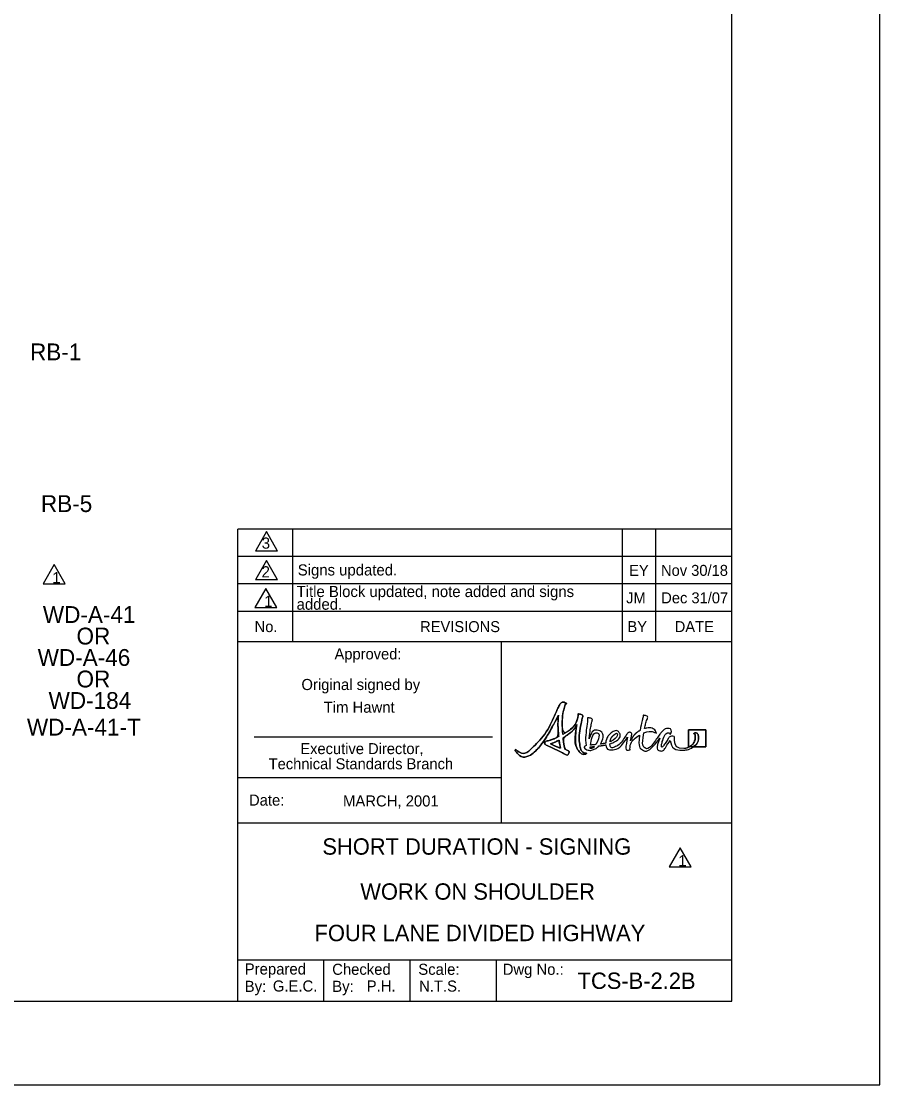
# Model space of a CAD drawing. Extents: x 1333 to 1549, y 120 to 399.
# Drawn here: x 1438.4 to 1549.4, y 119.8 to 257.2 of the extents above; entities that cross this region are included whole.
import ezdxf

# ---------------------------------------------------------------- set-up
doc = ezdxf.new("R2010")
doc.units = 0
for name, color, linetype in [('Level 1', 7, 'Continuous'), ('Level 10', 7, 'Continuous'), ('Level 2', 7, 'Continuous'), ('Level 22', 7, 'Continuous'), ('Level 44', 7, 'Continuous'), ('Level 45', 7, 'Continuous'), ('Level 53', 7, 'Continuous'), ('Level 60', 7, 'Continuous'), ('Level 63', 7, 'Continuous'), ('Level 7', 7, 'Continuous')]:
    doc.layers.add(name, color=color, linetype=linetype)

msp = doc.modelspace()

# ---------------------------------------------------------------- linework, layer by layer
at = {"layer": 'Level 1'}
for p, q in [((1466.39, 130.56), (1466.39, 177.03)), ((1500.44, 177.03), (1500.44, 153.62)), ((1466.39, 159.47), (1500.44, 159.47)), ((1466.39, 153.62), (1530.24, 153.62)), ((1466.39, 135.88), (1530.24, 135.88)), ((1477.52, 130.56), (1477.52, 135.88)), ((1488.65, 130.56), (1488.65, 135.88)), ((1499.78, 135.88), (1499.78, 130.56))]:
    msp.add_line(p, q, dxfattribs=at)
for points in [[(1442.64, 186.98), (1441.22, 184.51), (1444.06, 184.51)], [(1523.56, 150.39), (1522.14, 147.92), (1524.98, 147.92)]]:
    msp.add_lwpolyline(points, close=True, dxfattribs=at)
at = {"layer": 'Level 10'}
msp.add_line((1530.24, 130.56), (1530.24, 130.56), dxfattribs=at)
msp.add_line((1530.24, 130.56), (1530.24, 130.56), dxfattribs=at)
at = {"layer": 'Level 2'}
msp.add_line((1500.44, 177.03), (1500.44, 177.03), dxfattribs=at)
at = {"layer": 'Level 22'}
msp.add_line((1481.86, 130.56), (1481.86, 130.56), dxfattribs=at)
at = {"layer": 'Level 44'}
for p, q in [((1530.27, 191.58), (1466.38, 191.58)), ((1530.27, 188.03), (1466.38, 188.03)), ((1530.27, 184.48), (1466.38, 184.48)), ((1530.27, 180.93), (1466.38, 180.93)), ((1466.39, 177.03), (1530.27, 177.03))]:
    msp.add_line(p, q, dxfattribs=at)
msp.add_lwpolyline([(1470.01, 183.91), (1468.59, 181.44), (1471.43, 181.44)], close=True, dxfattribs=at)
at = {"layer": 'Level 45'}
msp.add_line((1500.46, 177.03), (1500.46, 177.03), dxfattribs=at)
at = {"layer": 'Level 53'}
msp.add_line((1525.26, 163.41), (1524.71, 163.41), dxfattribs=at)
msp.add_lwpolyline([(1525.26, 163.41), (1526.88, 163.41), (1526.88, 165.64), (1524.65, 165.64), (1524.65, 163.41), (1524.71, 163.41)], dxfattribs=at)
for points, degree in [([(1511.28, 162.6), (1511.04, 162.64), (1510.72, 162.97), (1510.63, 163.5), (1510.46, 164.47), (1510.56, 165.42), (1510.84, 166.84), (1510.89, 167.11), (1511.08, 167.58), (1510.49, 167.67), (1510.31, 167.7), (1510.41, 167.61), (1510.35, 167.36), (1510.13, 166.3), (1509.26, 165.54), (1508.39, 165.03), (1508.3, 166.24), (1508.34, 167.59), (1508.57, 168.41), (1508.76, 169.11), (1508.99, 168.98), (1508.71, 169.13), (1508.41, 169.28), (1508.09, 169.08), (1507.83, 168.56), (1507.57, 168.04), (1506.37, 165.22), (1504.46, 163.32), (1503.48, 162.35), (1502.6, 162.85), (1502.42, 163), (1502.27, 163.12), (1502.22, 162.93), (1502.4, 162.74), (1503.19, 161.89), (1504.35, 162.38), (1504.77, 162.8), (1505.93, 163.96), (1507.28, 166.46), (1507.83, 167.52), (1507.78, 166.93), (1507.76, 165.92), (1507.87, 164.75), (1507.28, 164.46), (1506.75, 164.29), (1506.5, 164.23), (1506.23, 164.15), (1506.06, 164.04), (1506.06, 163.92), (1506.05, 163.78), (1506.23, 163.66), (1506.5, 163.54), (1506.97, 163.32), (1508.34, 162.67), (1508.68, 162.47), (1508.96, 162.3), (1509.11, 162.44), (1509.19, 162.62), (1509.3, 162.85), (1509, 162.99), (1508.7, 163.08), (1508.58, 163.48), (1508.49, 164.01), (1508.43, 164.6), (1509.13, 165.03), (1509.82, 165.6), (1510.21, 166.32), (1510.11, 165.72), (1509.86, 163.69), (1510.5, 162.83), (1510.64, 162.64), (1510.95, 162.44), (1511.26, 162.47), (1511.4, 162.48), (1511.47, 162.57), (1511.46, 162.6), (1511.44, 162.63), (1511.36, 162.59), (1511.28, 162.6)], 3), ([(1508.39, 165.03), (1508.3, 166.24), (1508.34, 167.59), (1508.57, 168.41), (1508.76, 169.11), (1508.99, 168.98), (1508.71, 169.13), (1508.41, 169.28), (1508.09, 169.08), (1507.83, 168.56), (1507.57, 168.04), (1506.37, 165.22), (1504.46, 163.32), (1503.48, 162.35), (1502.6, 162.85), (1502.42, 163), (1502.27, 163.12), (1502.22, 162.93), (1502.4, 162.74), (1503.19, 161.89), (1504.35, 162.38), (1504.77, 162.8), (1505.93, 163.96), (1507.28, 166.46), (1507.83, 167.52)], 3), ([(1507.83, 167.52), (1507.78, 166.93), (1507.76, 165.92), (1507.87, 164.75)], 2), ([(1511.28, 162.6), (1511.04, 162.64), (1510.72, 162.97), (1510.63, 163.5), (1510.46, 164.47), (1510.56, 165.42), (1510.84, 166.84), (1510.89, 167.11), (1511.08, 167.58), (1510.49, 167.67), (1510.31, 167.7), (1510.41, 167.61), (1510.35, 167.36), (1510.13, 166.3), (1509.26, 165.54), (1508.39, 165.03)], 3), ([(1511.81, 164.45), (1511.86, 165.02), (1511.95, 165.71), (1512.08, 166.35), (1512.13, 166.62), (1512.32, 167.09), (1511.73, 167.17), (1511.55, 167.2), (1511.58, 167.12), (1511.59, 166.87), (1511.61, 166.53), (1511.24, 164.49), (1511.43, 163.59)], 3), ([(1518.97, 165.79), (1519.03, 166.08), (1519.11, 166.39), (1519.19, 166.68), (1519.26, 166.95), (1519.49, 167.42), (1518.91, 167.5), (1518.73, 167.53), (1518.8, 167.44), (1518.74, 167.2), (1518.63, 166.74), (1518.49, 166.15), (1518.39, 165.55)], 3), ([(1508.43, 164.6), (1509.13, 165.03), (1509.82, 165.6), (1510.21, 166.32)], 2), ([(1510.21, 166.32), (1510.11, 165.72), (1509.86, 163.69), (1510.5, 162.83), (1510.64, 162.64), (1510.95, 162.44), (1511.26, 162.47), (1511.4, 162.48), (1511.47, 162.57), (1511.46, 162.6), (1511.44, 162.63), (1511.36, 162.59), (1511.28, 162.6)], 3), ([(1513.25, 163.78), (1513.67, 164.46), (1513.63, 165.37), (1513.02, 165.52), (1512.32, 165.7), (1511.96, 165.01), (1511.81, 164.45)], 3), ([(1511.96, 163.66), (1512.06, 164.37), (1512.43, 165.37), (1512.89, 165.21), (1513.16, 165.11), (1513.02, 164.28), (1512.68, 163.72)], 3), ([(1514.48, 163.81), (1514.57, 163.84), (1514.66, 163.87), (1514.73, 163.9), (1515.61, 164.29), (1515.92, 164.88), (1515.69, 165.24), (1515.48, 165.58), (1514.87, 165.48), (1514.39, 164.97), (1514.15, 164.72), (1513.97, 164.29), (1513.95, 163.9)], 3), ([(1517.15, 164.22), (1517.21, 164.5), (1517.29, 164.8), (1517.3, 165.01), (1517.31, 165.23), (1517.16, 165.28), (1517.1, 165.29), (1516.97, 165.33), (1516.82, 165.27), (1516.67, 165.05), (1516.32, 164.56), (1515.87, 163.77), (1515.19, 163.44), (1514.7, 163.2), (1514.49, 163.44), (1514.48, 163.81)], 3), ([(1514.95, 164.93), (1515.24, 165.2), (1515.39, 165.18), (1515.43, 165.11), (1515.51, 164.95), (1515.17, 164.39), (1514.5, 164.08)], 3), ([(1518.39, 165.55), (1517.92, 165.28), (1517.47, 164.82), (1517.15, 164.22)], 2), ([(1524.02, 163.22), (1523.11, 163.22), (1522.87, 163.93), (1522.83, 164.28), (1522.8, 164.51), (1522.85, 164.85), (1522.44, 164.81), (1522.16, 164.78), (1521.9, 164.22), (1521.54, 163.76), (1521.24, 163.36), (1521.1, 163.4), (1521.17, 163.74), (1521.26, 164.17), (1521.62, 165.18), (1522.03, 165.25), (1522.22, 165.28), (1522.28, 164.95), (1522.37, 165.16), (1522.46, 165.37), (1522.38, 165.82), (1521.95, 165.82), (1521.66, 165.82), (1521.3, 165.5), (1521.01, 165.14), (1520.76, 164.83), (1519.47, 162.94), (1518.93, 163.35), (1518.68, 163.54), (1518.7, 164.32), (1518.86, 165.23)], 3), ([(1518.86, 165.23), (1519.5, 165.48), (1520.03, 165.4), (1520.33, 165.26), (1520.48, 165.18), (1520.5, 165.19), (1520.44, 165.36), (1520.34, 165.6), (1519.83, 165.97), (1519.02, 165.8), (1519.01, 165.8), (1518.99, 165.79), (1518.97, 165.79)], 3), ([(1524.65, 165.64), (1524.65, 165.64), (1524.65, 163.41), (1524.65, 163.41), (1524.65, 163.41), (1524.71, 163.41), (1524.71, 163.41), (1525.2, 163.7), (1525.52, 164.26), (1525.52, 164.71), (1525.52, 165.11), (1525.31, 165.09), (1525.33, 165.14), (1525.4, 165.3), (1525.9, 165.21), (1525.92, 164.65), (1525.95, 164.18), (1525.7, 163.73), (1525.26, 163.41), (1525.26, 163.41), (1526.88, 163.41), (1526.88, 163.41), (1526.88, 163.41), (1526.88, 165.64), (1526.88, 165.64), (1526.88, 165.64), (1524.65, 165.64), (1524.65, 165.64)], 3), ([(1524.71, 163.41), (1525.2, 163.7), (1525.52, 164.26), (1525.52, 164.71), (1525.52, 165.11), (1525.31, 165.09), (1525.33, 165.14), (1525.4, 165.3), (1525.9, 165.21), (1525.92, 164.65), (1525.95, 164.18), (1525.7, 163.73), (1525.26, 163.41)], 3), ([(1507.87, 164.75), (1507.28, 164.46), (1506.75, 164.29), (1506.5, 164.23), (1506.23, 164.15), (1506.06, 164.04), (1506.06, 163.92), (1506.05, 163.78), (1506.23, 163.66), (1506.5, 163.54), (1506.97, 163.32), (1508.34, 162.67), (1508.68, 162.47), (1508.96, 162.3), (1509.11, 162.44), (1509.19, 162.62), (1509.3, 162.85), (1509, 162.99), (1508.7, 163.08)], 3), ([(1506.8, 163.82), (1507.11, 163.93), (1507.51, 164.09), (1507.92, 164.31)], 2), ([(1506.8, 163.82), (1507.11, 163.93), (1507.51, 164.09), (1507.92, 164.31), (1507.98, 163.84), (1508.04, 163.5), (1508.1, 163.24), (1507.8, 163.35), (1507.37, 163.53), (1506.8, 163.82)], 3), ([(1508.1, 163.24), (1507.8, 163.35), (1507.37, 163.53), (1506.8, 163.82)], 2), ([(1507.92, 164.31), (1507.98, 163.84), (1508.04, 163.5), (1508.1, 163.24)], 2), ([(1508.7, 163.08), (1508.58, 163.48), (1508.49, 164.01), (1508.43, 164.6)], 2), ([(1511.43, 163.59), (1511.18, 163.51), (1511.08, 163.32), (1511.4, 163.12), (1511.63, 162.99), (1512.12, 162.94), (1512.61, 163.19), (1512.79, 163.27), (1512.94, 163.4), (1513.07, 163.54)], 3), ([(1512.68, 163.72), (1512.45, 163.7), (1512.21, 163.67), (1511.96, 163.66)], 2), ([(1513.07, 163.54), (1513.36, 163.58), (1513.67, 163.63), (1513.96, 163.68)], 2), ([(1513.95, 163.9), (1513.75, 163.86), (1513.51, 163.82), (1513.25, 163.78)], 2), ([(1513.96, 163.68), (1514.01, 163.29), (1514.26, 162.99), (1514.86, 163.04), (1515.7, 163.12), (1516.45, 164.16), (1516.74, 164.66)], 3), ([(1514.5, 164.08), (1514.56, 164.38), (1514.72, 164.71), (1514.95, 164.93)], 2), ([(1516.74, 164.66), (1516.69, 164.13), (1516.34, 162.95), (1516.93, 163.01), (1517.17, 163.04), (1517.07, 163.07), (1517.08, 163.28), (1517.13, 163.98), (1517.72, 164.58), (1518.3, 164.95)], 3), ([(1518.3, 164.95), (1518.2, 164.08), (1518.24, 163.31), (1518.63, 163.07), (1519.35, 162.61), (1520.37, 163.8), (1520.94, 164.53)], 3), ([(1520.94, 164.53), (1520.65, 163.88), (1520.49, 163.06), (1520.92, 162.93), (1521.42, 162.78), (1521.82, 163.62), (1522.29, 164.26)], 3), ([(1522.29, 164.26), (1522.34, 163.8), (1522.65, 163.01), (1523.88, 163.01), (1524.44, 163.01), (1524.91, 163.17), (1525.26, 163.41)], 3), ([(1511.89, 163.22), (1511.92, 163.25), (1511.94, 163.29), (1511.94, 163.34), (1511.94, 163.37), (1511.94, 163.4), (1511.94, 163.43)], 3), ([(1512.09, 163.23), (1512.01, 163.21), (1511.94, 163.21), (1511.89, 163.22)], 2), ([(1511.94, 163.43), (1512.07, 163.44), (1512.26, 163.45), (1512.5, 163.48)], 2), ([(1512.5, 163.48), (1512.38, 163.34), (1512.24, 163.25), (1512.09, 163.23)], 2), ([(1524.71, 163.41), (1524.51, 163.29), (1524.27, 163.22), (1524.02, 163.22)], 2)]:
    msp.add_open_spline(points, degree=degree, dxfattribs=at)
at = {"layer": 'Level 60'}
for points in [[(1549.36, 398.75), (1333.36, 398.75), (1333.36, 119.75), (1549.36, 119.75)], [(1530.24, 387.94), (1343.36, 387.94), (1343.36, 130.56), (1530.24, 130.56)]]:
    msp.add_lwpolyline(points, close=True, dxfattribs=at)
at = {"layer": 'Level 63'}
for p, q in [((1466.39, 185.1), (1466.39, 191.58)), ((1473.48, 185.1), (1473.48, 191.58)), ((1516.07, 191.58), (1516.07, 177.03)), ((1520.38, 191.58), (1520.38, 177.03)), ((1466.39, 177.03), (1466.39, 185.1)), ((1473.48, 177.03), (1473.48, 185.1))]:
    msp.add_line(p, q, dxfattribs=at)
for points in [[(1470.09, 191.25), (1468.7, 188.82)], [(1471.49, 188.82), (1470.09, 191.25)], [(1468.7, 188.82), (1468.67, 188.78), (1471.51, 188.78), (1471.49, 188.82)], [(1470.09, 187.53), (1468.7, 185.1)], [(1471.49, 185.1), (1470.09, 187.53)], [(1468.7, 185.1), (1468.67, 185.06), (1471.51, 185.06), (1471.49, 185.1)]]:
    msp.add_lwpolyline(points, dxfattribs=at)
at = {"layer": 'Level 7'}
msp.add_line((1468.5, 164.71), (1499.3, 164.71), dxfattribs=at)

# ---------------------------------------------------------------- texts
at = {"layer": 'Level 1'}
for s, height, p in [('Signs updated.', 1.44, (1474.14, 185.58)), ('1', 1.45, (1442.41, 184.57)), ('Title Block updated, note added and signs ', 1.44, (1473.99, 182.79)), ('added.', 1.44, (1473.99, 181.15)), ('Date:', 1.433, (1467.83, 155.83)), ('1', 1.45, (1523.33, 147.98)), ('Prepared', 1.44, (1467.28, 134)), ('Checked', 1.433, (1478.59, 133.96)), ('Scale:', 1.433, (1489.72, 133.96)), ('Dwg No.:', 1.433, (1500.63, 133.96)), ('By:', 1.44, (1467.28, 131.75)), ('By:', 1.44, (1478.59, 131.75)), ('    N.T.S.   ', 1.4329, (1487.69, 131.79))]:
    msp.add_text(s, height=height, rotation=360, dxfattribs=at).set_placement(p)
at = {"layer": 'Level 10'}
for s, height, p in [('RB-1', 2.177, (1439.53, 213.39)), ('RB-5', 2.177, (1440.94, 193.78)), ('WD-A-41', 2.177, (1441.19, 179.44)), ('OR', 2.177, (1445.54, 176.66)), ('WD-A-46', 2.177, (1440.52, 173.89)), ('OR', 2.177, (1445.54, 171.11)), ('WD-184', 2.177, (1441.93, 168.33)), ('WD-A-41-T', 2.177, (1439.13, 164.89)), ('SHORT DURATION - SIGNING', 2.115, (1477.32, 149.49)), ('WORK ON SHOULDER', 2.115, (1482.22, 143.67)), ('FOUR LANE DIVIDED HIGHWAY', 2.1152, (1476.31, 138.31))]:
    msp.add_text(s, height=height, rotation=360, dxfattribs=at).set_placement(p)
at = {"layer": 'Level 44'}
for s, height, p in [('3', 1.45, (1469.48, 189.04)), ('Nov 30/18', 1.419, (1521.09, 185.53)), ('2', 1.45, (1469.46, 185.33)), ('EY', 1.419, (1516.97, 185.53)), ('1', 1.45, (1469.79, 181.5)), ('JM', 1.419, (1516.58, 181.98)), ('Dec 31/07', 1.419, (1521.12, 181.98)), ('No.', 1.419, (1468.56, 178.26)), ('REVISIONS', 1.419, (1489.95, 178.26)), ('BY', 1.419, (1516.75, 178.26)), ('DATE', 1.419, (1522.86, 178.26))]:
    msp.add_text(s, height=height, rotation=360, dxfattribs=at).set_placement(p)
at = {"layer": 'Level 60'}
for s, height, p in [('MARCH, 2001', 1.434, (1479.99, 155.72)), ('TCS-B-2.2B', 2.115, (1510.31, 132.14))]:
    msp.add_text(s, height=height, dxfattribs=at).set_placement(p)
for s, p in [('G.E.C.', (1470.92, 131.8)), ('P.H.', (1483.05, 131.8))]:
    msp.add_text(s, height=1.433, rotation=360, dxfattribs=at).set_placement(p)
at = {"layer": 'Level 7'}
for s, height, p in [('Approved:', 1.419, (1478.89, 174.73)), ('Original signed by', 1.434, (1474.61, 170.77)), ('Tim Hawnt', 1.434, (1477.5, 167.84)), ('Executive Director,', 1.4187, (1474.47, 162.49)), ('Technical Standards Branch', 1.4187, (1470.38, 160.53))]:
    msp.add_text(s, height=height, dxfattribs=at).set_placement(p)

doc.saveas('drawing.dxf')
